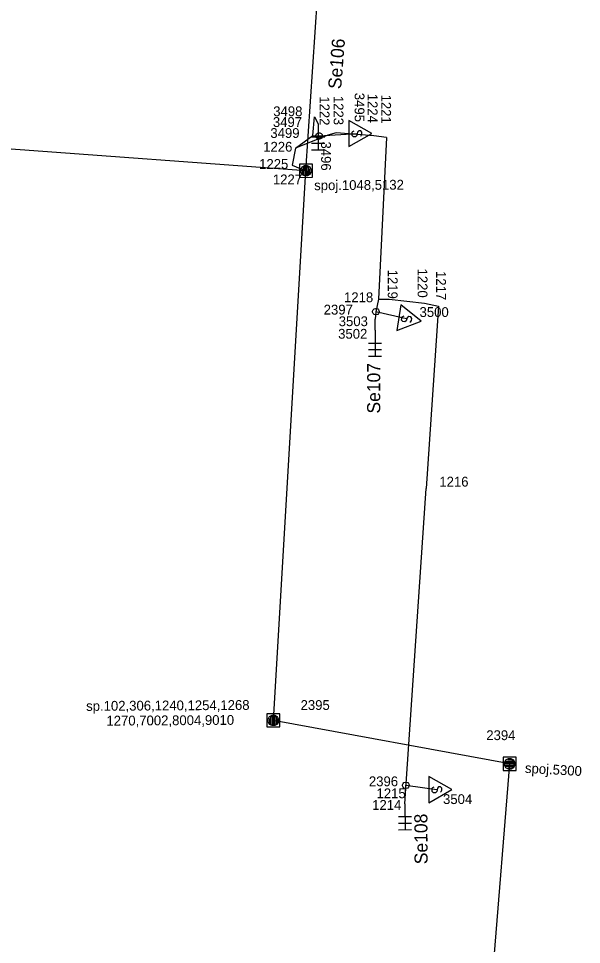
# Model space of a CAD drawing. Extents: x -535557 to -534097, y -1142175 to -1136716.
# Drawn here: x -534453.3 to -534410.3, y -1140816.1 to -1140745.3 of the extents above; entities that cross this region are included whole.
import ezdxf

# ---------------------------------------------------------------- set-up
doc = ezdxf.new("R2010")
doc.units = 0
doc.layers.add('Default', color=7, linetype='Continuous')
doc.layers.add('SS_SZDC', color=7, linetype='Continuous')

# ---------------------------------------------------------------- blocks, each defined once
blk = doc.blocks.new('POINT_DISPLAY')
at = {"layer": 'Default'}
blk.add_line((0, 0), (0, 0), dxfattribs=at)

msp = doc.modelspace()

# ---------------------------------------------------------------- linework, layer by layer
at = {"layer": 'SS_SZDC'}
for p, q in [((-534431.31, -1140756.95), (-534427.689, -1140702.69)), ((-534430.789, -1140754.25), (-534430.67, -1140752.819)), ((-534430.67, -1140752.819), (-534430.38, -1140753.37)), ((-534431.31, -1140756.95), (-534477.67, -1140753.54)), ((-534430.38, -1140753.37), (-534430.38, -1140755.37)), ((-534428.03, -1140753.1), (-534428.03, -1140755.1)), ((-534426.28, -1140754.1), (-534428.03, -1140753.1)), ((-534429.649, -1140754.219), (-534432.119, -1140755.219)), ((-534432.119, -1140755.219), (-534430.789, -1140754.25)), ((-534430.789, -1140754.25), (-534430.31, -1140754.29)), ((-534430.556, -1140754.332), (-534430.555, -1140754.221)), ((-534430.534, -1140754.4), (-534430.556, -1140754.332)), ((-534430.555, -1140754.221), (-534430.51, -1140754.131)), ((-534430.51, -1140754.131), (-534430.42, -1140754.065)), ((-534430.42, -1140754.065), (-534430.352, -1140754.043)), ((-534430.352, -1140754.043), (-534430.241, -1140754.044)), ((-534430.31, -1140754.29), (-534427.43, -1140754.1)), ((-534430.241, -1140754.044), (-534430.151, -1140754.089)), ((-534430.151, -1140754.089), (-534430.085, -1140754.179)), ((-534430.085, -1140754.179), (-534430.063, -1140754.247)), ((-534430.063, -1140754.247), (-534430.064, -1140754.358)), ((-534429.01, -1140754.049), (-534429.649, -1140754.219)), ((-534426.13, -1140754.27), (-534429.01, -1140754.049)), ((-534428.03, -1140755.1), (-534426.28, -1140754.1)), ((-534427.78, -1140754), (-534427.73, -1140753.95)), ((-534427.78, -1140754.25), (-534427.78, -1140754)), ((-534427.68, -1140754.35), (-534427.78, -1140754.25)), ((-534427.73, -1140753.95), (-534427.63, -1140753.9)), ((-534427.53, -1140754.35), (-534427.68, -1140754.35)), ((-534427.43, -1140754.25), (-534427.53, -1140754.35)), ((-534427.38, -1140754), (-534427.43, -1140754.25)), ((-534427.28, -1140753.9), (-534427.38, -1140754)), ((-534427.13, -1140753.9), (-534427.28, -1140753.9)), ((-534427.03, -1140754), (-534427.13, -1140753.9)), ((-534427.13, -1140754.3), (-534427.08, -1140754.25)), ((-534427.08, -1140754.25), (-534427.03, -1140754.15)), ((-534427.03, -1140754.15), (-534427.03, -1140754)), ((-534425.149, -1140754.409), (-534426.13, -1140754.27)), ((-534429.88, -1140754.37), (-534430.88, -1140754.37)), ((-534429.88, -1140754.87), (-534430.88, -1140754.87)), ((-534430.468, -1140754.49), (-534430.534, -1140754.4)), ((-534430.378, -1140754.535), (-534430.468, -1140754.49)), ((-534430.267, -1140754.536), (-534430.378, -1140754.535)), ((-534430.199, -1140754.514), (-534430.267, -1140754.536)), ((-534430.109, -1140754.448), (-534430.199, -1140754.514)), ((-534430.064, -1140754.358), (-534430.109, -1140754.448)), ((-534425.149, -1140754.409), (-534425.76, -1140766.76)), ((-534432.119, -1140755.219), (-534432.359, -1140756.52)), ((-534429.88, -1140755.37), (-534430.88, -1140755.37)), ((-534430.813, -1140756.446), (-534431.813, -1140756.453)), ((-534431.813, -1140756.453), (-534431.806, -1140757.453)), ((-534430.806, -1140757.446), (-534430.813, -1140756.446)), ((-534433.8, -1140798.979), (-534431.31, -1140756.95)), ((-534432.359, -1140756.52), (-534431.31, -1140756.95)), ((-534431.71, -1140756.852), (-534431.611, -1140756.651)), ((-534431.709, -1140757.052), (-534431.71, -1140756.852)), ((-534431.608, -1140757.251), (-534431.709, -1140757.052)), ((-534431.611, -1140756.651), (-534431.412, -1140756.55)), ((-534431.61, -1140756.801), (-534431.609, -1140757.101)), ((-534431.609, -1140757.101), (-534431.508, -1140757.251)), ((-534431.511, -1140756.701), (-534431.412, -1140756.6)), ((-534431.508, -1140757.251), (-534431.511, -1140756.701)), ((-534431.412, -1140756.55), (-534431.212, -1140756.549)), ((-534431.412, -1140756.6), (-534431.407, -1140757.3)), ((-534431.307, -1140757.299), (-534431.312, -1140756.6)), ((-534431.212, -1140756.549), (-534431.011, -1140756.648)), ((-534431.207, -1140757.299), (-534431.212, -1140756.599)), ((-534431.212, -1140756.599), (-534431.111, -1140756.698)), ((-534431.111, -1140756.698), (-534431.108, -1140757.248)), ((-534431.108, -1140757.248), (-534431.009, -1140757.098)), ((-534431.011, -1140756.648), (-534430.91, -1140756.847)), ((-534431.009, -1140757.098), (-534431.01, -1140756.798)), ((-534430.909, -1140757.047), (-534431.008, -1140757.248)), ((-534430.91, -1140756.847), (-534430.909, -1140757.047)), ((-534431.806, -1140757.453), (-534430.806, -1140757.446)), ((-534431.407, -1140757.35), (-534431.608, -1140757.251)), ((-534431.407, -1140757.3), (-534431.207, -1140757.299)), ((-534431.207, -1140757.349), (-534431.407, -1140757.35)), ((-534431.008, -1140757.248), (-534431.207, -1140757.349)), ((-534425.76, -1140766.76), (-534425.97, -1140767.729)), ((-534425.76, -1140766.76), (-534424.96, -1140766.77)), ((-534424.96, -1140766.77), (-534422.25, -1140767.069)), ((-534422.25, -1140767.069), (-534421.17, -1140767.299)), ((-534426.217, -1140767.694), (-534426.182, -1140767.588)), ((-534426.217, -1140767.765), (-534426.217, -1140767.694)), ((-534426.182, -1140767.871), (-534426.217, -1140767.765)), ((-534426.182, -1140767.588), (-534426.111, -1140767.517)), ((-534426.111, -1140767.517), (-534426.005, -1140767.482)), ((-534425.97, -1140767.729), (-534426.029, -1140768.299)), ((-534426.005, -1140767.482), (-534425.934, -1140767.482)), ((-534423.63, -1140768.28), (-534425.97, -1140767.729)), ((-534425.934, -1140767.482), (-534425.828, -1140767.517)), ((-534425.828, -1140767.517), (-534425.757, -1140767.588)), ((-534425.757, -1140767.588), (-534425.722, -1140767.694)), ((-534425.722, -1140767.765), (-534425.757, -1140767.871)), ((-534425.722, -1140767.694), (-534425.722, -1140767.765)), ((-534424.066, -1140767.198), (-534424.379, -1140769.173)), ((-534422.494, -1140768.459), (-534424.066, -1140767.198)), ((-534421.17, -1140767.299), (-534422.119, -1140781.25)), ((-534426.111, -1140767.942), (-534426.182, -1140767.871)), ((-534426.005, -1140767.977), (-534426.111, -1140767.942)), ((-534426.029, -1140769.149), (-534426.029, -1140768.299)), ((-534425.934, -1140767.977), (-534426.005, -1140767.977)), ((-534425.828, -1140767.942), (-534425.934, -1140767.977)), ((-534425.757, -1140767.871), (-534425.828, -1140767.942)), ((-534424.379, -1140769.173), (-534422.494, -1140768.459)), ((-534423.999, -1140768.373), (-534423.96, -1140768.126)), ((-534423.916, -1140768.487), (-534423.999, -1140768.373)), ((-534423.96, -1140768.126), (-534423.902, -1140768.084)), ((-534423.767, -1140768.511), (-534423.916, -1140768.487)), ((-534423.902, -1140768.084), (-534423.796, -1140768.051)), ((-534423.653, -1140768.428), (-534423.767, -1140768.511)), ((-534423.564, -1140768.189), (-534423.653, -1140768.428)), ((-534423.45, -1140768.105), (-534423.564, -1140768.189)), ((-534423.302, -1140768.129), (-534423.45, -1140768.105)), ((-534423.364, -1140768.524), (-534423.307, -1140768.482)), ((-534423.307, -1140768.482), (-534423.242, -1140768.391)), ((-534423.219, -1140768.243), (-534423.302, -1140768.129)), ((-534423.242, -1140768.391), (-534423.219, -1140768.243)), ((-534426.029, -1140769.149), (-534426.029, -1140771.149)), ((-534425.529, -1140770.149), (-534426.529, -1140770.149)), ((-534425.529, -1140770.649), (-534426.529, -1140770.649)), ((-534425.529, -1140771.149), (-534426.529, -1140771.149)), ((-534423.71, -1140804.579), (-534422.119, -1140781.25)), ((-534433.3, -1140798.479), (-534434.3, -1140798.479)), ((-534434.3, -1140798.479), (-534434.3, -1140799.479)), ((-534434.2, -1140798.882), (-534434.101, -1140798.681)), ((-534434.199, -1140799.082), (-534434.2, -1140798.882)), ((-534434.101, -1140798.681), (-534433.902, -1140798.58)), ((-534434.1, -1140798.831), (-534434.099, -1140799.131)), ((-534434.001, -1140798.731), (-534433.902, -1140798.63)), ((-534433.998, -1140799.281), (-534434.001, -1140798.731)), ((-534433.902, -1140798.58), (-534433.702, -1140798.579)), ((-534433.902, -1140798.63), (-534433.897, -1140799.33)), ((-534433.797, -1140799.329), (-534433.802, -1140798.63)), ((-534433.702, -1140798.579), (-534433.501, -1140798.678)), ((-534433.697, -1140799.329), (-534433.702, -1140798.629)), ((-534433.702, -1140798.629), (-534433.601, -1140798.728)), ((-534433.601, -1140798.728), (-534433.598, -1140799.278)), ((-534433.501, -1140798.678), (-534433.4, -1140798.877)), ((-534433.499, -1140799.128), (-534433.5, -1140798.828)), ((-534433.4, -1140798.877), (-534433.399, -1140799.077)), ((-534433.3, -1140799.479), (-534433.3, -1140798.479)), ((-534434.3, -1140799.479), (-534433.3, -1140799.479)), ((-534434.098, -1140799.281), (-534434.199, -1140799.082)), ((-534434.099, -1140799.131), (-534433.998, -1140799.281)), ((-534433.897, -1140799.38), (-534434.098, -1140799.281)), ((-534433.897, -1140799.33), (-534433.697, -1140799.329)), ((-534433.697, -1140799.379), (-534433.897, -1140799.38)), ((-534415.739, -1140802.299), (-534433.8, -1140798.979)), ((-534433.498, -1140799.278), (-534433.697, -1140799.379)), ((-534433.598, -1140799.278), (-534433.499, -1140799.128)), ((-534433.399, -1140799.077), (-534433.498, -1140799.278)), ((-534419.489, -1140849.489), (-534415.739, -1140802.299)), ((-534415.239, -1140801.799), (-534416.239, -1140801.799)), ((-534416.239, -1140801.799), (-534416.239, -1140802.799)), ((-534416.14, -1140802.202), (-534416.041, -1140802.001)), ((-534416.139, -1140802.402), (-534416.14, -1140802.202)), ((-534416.038, -1140802.601), (-534416.139, -1140802.402)), ((-534416.09, -1140802.202), (-534415.991, -1140802.101)), ((-534415.39, -1140802.197), (-534416.09, -1140802.202)), ((-534415.39, -1140802.297), (-534416.089, -1140802.302)), ((-534416.089, -1140802.402), (-534415.389, -1140802.397)), ((-534415.988, -1140802.501), (-534416.089, -1140802.402)), ((-534416.041, -1140802.001), (-534415.842, -1140801.9)), ((-534415.991, -1140802.101), (-534415.441, -1140802.098)), ((-534415.438, -1140802.498), (-534415.988, -1140802.501)), ((-534415.591, -1140801.999), (-534415.891, -1140802)), ((-534415.842, -1140801.9), (-534415.642, -1140801.899)), ((-534415.642, -1140801.899), (-534415.441, -1140801.998)), ((-534415.441, -1140802.098), (-534415.591, -1140801.999)), ((-534415.588, -1140802.599), (-534415.438, -1140802.498)), ((-534415.441, -1140801.998), (-534415.34, -1140802.197)), ((-534415.339, -1140802.397), (-534415.438, -1140802.598)), ((-534415.389, -1140802.397), (-534415.39, -1140802.197)), ((-534415.34, -1140802.197), (-534415.339, -1140802.397)), ((-534415.239, -1140802.799), (-534415.239, -1140801.799)), ((-534416.239, -1140802.799), (-534415.239, -1140802.799)), ((-534415.837, -1140802.7), (-534416.038, -1140802.601)), ((-534415.888, -1140802.6), (-534415.588, -1140802.599)), ((-534415.637, -1140802.699), (-534415.837, -1140802.7)), ((-534415.438, -1140802.598), (-534415.637, -1140802.699)), ((-534423.927, -1140803.904), (-534423.892, -1140803.798)), ((-534423.927, -1140803.975), (-534423.927, -1140803.904)), ((-534423.892, -1140803.798), (-534423.821, -1140803.727)), ((-534423.821, -1140803.727), (-534423.715, -1140803.692)), ((-534423.715, -1140803.692), (-534423.644, -1140803.692)), ((-534423.644, -1140803.692), (-534423.538, -1140803.727)), ((-534423.538, -1140803.727), (-534423.467, -1140803.798)), ((-534423.467, -1140803.798), (-534423.432, -1140803.904)), ((-534423.432, -1140803.904), (-534423.432, -1140803.975)), ((-534421.919, -1140803.27), (-534421.919, -1140805.27)), ((-534420.169, -1140804.27), (-534421.919, -1140803.27)), ((-534423.892, -1140804.081), (-534423.927, -1140803.975)), ((-534423.821, -1140804.152), (-534423.892, -1140804.081)), ((-534423.715, -1140804.187), (-534423.821, -1140804.152)), ((-534423.75, -1140805.36), (-534423.71, -1140804.579)), ((-534423.644, -1140804.187), (-534423.715, -1140804.187)), ((-534423.71, -1140804.579), (-534423.68, -1140803.94)), ((-534423.68, -1140803.94), (-534421.319, -1140804.27)), ((-534423.538, -1140804.152), (-534423.644, -1140804.187)), ((-534423.467, -1140804.081), (-534423.538, -1140804.152)), ((-534423.432, -1140803.975), (-534423.467, -1140804.081)), ((-534421.919, -1140805.27), (-534420.169, -1140804.27)), ((-534421.669, -1140804.17), (-534421.619, -1140804.12)), ((-534421.669, -1140804.42), (-534421.669, -1140804.17)), ((-534421.569, -1140804.52), (-534421.669, -1140804.42)), ((-534421.619, -1140804.12), (-534421.519, -1140804.07)), ((-534421.419, -1140804.52), (-534421.569, -1140804.52)), ((-534421.319, -1140804.42), (-534421.419, -1140804.52)), ((-534421.269, -1140804.17), (-534421.319, -1140804.42)), ((-534421.169, -1140804.07), (-534421.269, -1140804.17)), ((-534421.019, -1140804.07), (-534421.169, -1140804.07)), ((-534420.919, -1140804.17), (-534421.019, -1140804.07)), ((-534421.019, -1140804.47), (-534420.969, -1140804.42)), ((-534420.969, -1140804.42), (-534420.919, -1140804.32)), ((-534420.919, -1140804.32), (-534420.919, -1140804.17)), ((-534423.75, -1140805.36), (-534423.736, -1140807.359)), ((-534423.243, -1140806.356), (-534424.243, -1140806.363)), ((-534423.24, -1140806.856), (-534424.24, -1140806.863)), ((-534423.236, -1140807.356), (-534424.236, -1140807.363))]:
    msp.add_line(p, q, dxfattribs=at)

# ---------------------------------------------------------------- block references
for p in [(-534430.67, -1140752.819), (-534430.38, -1140753.37), (-534430.789, -1140754.25), (-534430.31, -1140754.29), (-534430.31, -1140754.29), (-534429.649, -1140754.219), (-534429.01, -1140754.049), (-534427.43, -1140754.1), (-534426.13, -1140754.27), (-534425.149, -1140754.409), (-534432.119, -1140755.219), (-534432.359, -1140756.52), (-534431.31, -1140756.95), (-534425.76, -1140766.76), (-534424.96, -1140766.77), (-534422.25, -1140767.069), (-534425.97, -1140767.729), (-534425.97, -1140767.729), (-534421.17, -1140767.299), (-534426.029, -1140768.299), (-534423.63, -1140768.28), (-534426.029, -1140769.149), (-534422.119, -1140781.25), (-534433.8, -1140798.979), (-534415.739, -1140802.299), (-534423.71, -1140804.579), (-534423.68, -1140803.94), (-534423.68, -1140803.94), (-534421.319, -1140804.27), (-534423.75, -1140805.36)]:
    msp.add_blockref('POINT_DISPLAY', p, dxfattribs=at)

# ---------------------------------------------------------------- texts
for s, height, rotation, p in [('Se106', 1, 85.5, (-534428.624, -1140750.733)), ('1222', 0.75, 270, (-534430.264, -1140751.257)), ('1223', 0.75, 270, (-534429.197, -1140751.225)), ('3495', 0.75, 270, (-534427.592, -1140750.989)), ('1224', 0.75, 270, (-534426.59, -1140751.06)), ('1221', 0.75, 270, (-534425.56, -1140751.125)), ('3496', 0.75, 270, (-534430.153, -1140754.713)), ('spoj.1048,5132', 0.74999, 0.37563, (-534430.683, -1140758.436)), ('1219', 0.75, 270, (-534425.057, -1140764.514)), ('1220', 0.75, 270, (-534422.775, -1140764.427)), ('1217', 0.75, 270, (-534421.364, -1140764.616)), ('Se107', 1, 90, (-534425.634, -1140775.515)), ('sp.102,306,1240,1254,1268', 0.74999, 0.37563, (-534448.113, -1140798.252)), ('1270,7002,8004,9010', 0.74999, 0.37563, (-534446.563, -1140799.379)), ('spoj.5300', 0.75, 356.77563, (-534414.588, -1140802.987)), ('Se108', 1, 90.37563, (-534422.009, -1140809.973))]:
    msp.add_text(s, height=height, rotation=rotation, dxfattribs=at).set_placement(p)
for s, p in [('3498', (-534433.814, -1140752.778)), ('3497', (-534433.84, -1140753.601)), ('3499', (-534434.035, -1140754.441)), ('1226', (-534434.581, -1140755.492)), ('1225', (-534434.893, -1140756.806)), ('1227', (-534433.842, -1140757.987)), ('1218', (-534428.402, -1140767)), ('2397', (-534429.957, -1140767.945)), ('3500', (-534422.63, -1140768.13)), ('3503', (-534428.809, -1140768.832)), ('3502', (-534428.852, -1140769.792)), ('1216', (-534421.119, -1140781.099)), ('2395', (-534431.723, -1140798.179)), ('2394', (-534417.529, -1140800.484)), ('2396', (-534426.501, -1140804.012)), ('1215', (-534425.918, -1140804.928)), ('3504', (-534420.834, -1140805.373)), ('1214', (-534426.251, -1140805.817))]:
    msp.add_text(s, height=0.75, dxfattribs=at).set_placement(p)

doc.saveas('drawing.dxf')
